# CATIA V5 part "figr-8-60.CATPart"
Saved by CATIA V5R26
Part number: Part1
Bounding box of the stored display mesh (mm): x -50.499 to 50.499, y -68.48 to 68.48, z 0 to 20
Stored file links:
  D:\_Deepak\CATIA\CATIA V5-6R2016_Deepak\Resources\Part files\Partfiles\c08_catia_v5_6r2016_prt\figr-8-60.CATPart
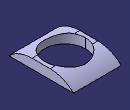
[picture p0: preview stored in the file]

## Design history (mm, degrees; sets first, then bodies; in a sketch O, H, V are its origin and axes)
Body1 (main body)
  Sketch1 on xy-plane, origin (0, 0, 0), H (1, 0, 0), V (0, 1, 0)
    line L1 (-50.499, 68.4797) -> (50.499, 68.4797)
    line L2 (50.499, 68.4797) -> (50.499, -68.4797)
    line L3 (50.499, -68.4797) -> (-50.499, -68.4797)
    line L4 (-50.499, -68.4797) -> (-50.499, 68.4797)
    axis line L5 (50.499, -68.4797) -> (-50.499, 68.4797)
    horizontal: L1 H, L3 H
    vertical: L2 V, L4 V
    midpoint: O L5
  Pad1: profile Sketch1, direction (0, 0, 1), length 20
  Fillet1: radius 71, on edge [face of Pad1 | face of Pad1]
  Fillet2: radius 71, on edge [face of Pad1 | face of Pad1]
  Body2
    Sketch2 on xy-plane, origin (0, 0, 0), H (1, 0, 0), V (0, 1, 0)
      circle A1 centre (0, 0) radius 43.2524
      point P1 (0, 43.2524)
      coincidence: A1 P1, P1 V
    Pocket1: profile Sketch2, direction (0, 0, -1), length 50, mirrored extent
  Assemble1: tool Body2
